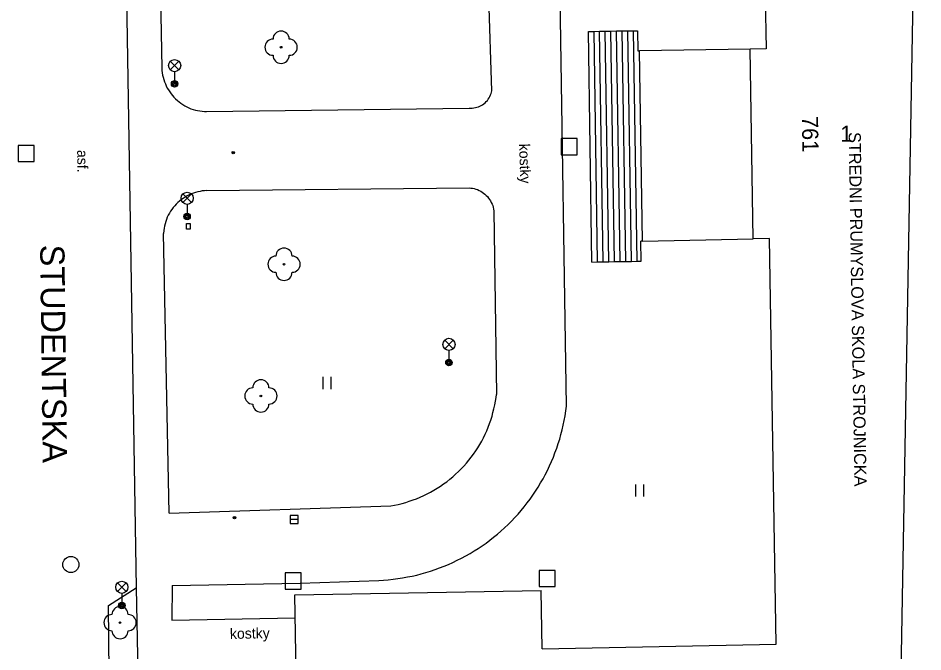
# Model space of a CAD drawing. Extents: x -641829 to -641525, y -1114855 to -1114359.
# Drawn here: x -641581.2 to -641525.3, y -1114437 to -1114397.8 of the extents above; entities that cross this region are included whole.
import ezdxf

# ---------------------------------------------------------------- set-up
doc = ezdxf.new("R2010")
doc.units = 0
for name, color, linetype in [('Vrstva 1', 7, 'Continuous'), ('Vrstva 10', 7, 'Continuous'), ('Vrstva 11', 7, 'Continuous'), ('Vrstva 20', 7, 'Continuous'), ('Vrstva 22', 7, 'Continuous'), ('Vrstva 24', 7, 'Continuous'), ('Vrstva 26', 7, 'Continuous'), ('Vrstva 27', 7, 'Continuous'), ('Vrstva 33', 7, 'Continuous'), ('Vrstva 36', 7, 'Continuous'), ('Vrstva 40', 7, 'Continuous'), ('Vrstva 41', 7, 'Continuous'), ('Vrstva 46', 7, 'Continuous'), ('Vrstva 47', 7, 'Continuous'), ('Vrstva 49', 7, 'Continuous'), ('Vrstva 5', 7, 'Continuous')]:
    doc.layers.add(name, color=color, linetype=linetype)

msp = doc.modelspace()

# ---------------------------------------------------------------- linework, layer by layer
at = {"layer": 'Vrstva 1'}
msp.add_line((-641533.66, -1114832.21), (-641525.3, -1114362.64), dxfattribs=at)
at = {"layer": 'Vrstva 10'}
for p, q in [((-641574.78, -1114379.56), (-641573.9, -1114433.06)), ((-641572.61, -1114384.05), (-641572.32, -1114400.95)), ((-641551.93, -1114402.34), (-641552.29, -1114391.15)), ((-641547.32, -1114421.83), (-641547.78, -1114391.56)), ((-641572.32, -1114400.95), (-641572.31, -1114401.09)), ((-641572.31, -1114401.09), (-641572.29, -1114401.23)), ((-641572.29, -1114401.23), (-641572.27, -1114401.37)), ((-641572.27, -1114401.37), (-641572.24, -1114401.51)), ((-641572.24, -1114401.51), (-641572.2, -1114401.64)), ((-641572.2, -1114401.64), (-641572.16, -1114401.78)), ((-641572.16, -1114401.78), (-641572.1, -1114401.91)), ((-641572.1, -1114401.91), (-641572.05, -1114402.04)), ((-641572.05, -1114402.04), (-641571.98, -1114402.17)), ((-641571.98, -1114402.17), (-641571.91, -1114402.29)), ((-641571.91, -1114402.29), (-641571.83, -1114402.41)), ((-641571.83, -1114402.41), (-641571.75, -1114402.52)), ((-641571.75, -1114402.52), (-641571.66, -1114402.64)), ((-641571.66, -1114402.64), (-641571.57, -1114402.74)), ((-641571.57, -1114402.74), (-641571.47, -1114402.84)), ((-641552.15, -1114402.86), (-641552.1, -1114402.78)), ((-641552.1, -1114402.78), (-641552.05, -1114402.69)), ((-641552.05, -1114402.69), (-641552.01, -1114402.6)), ((-641552.01, -1114402.6), (-641551.98, -1114402.51)), ((-641551.98, -1114402.51), (-641551.95, -1114402.42)), ((-641551.95, -1114402.42), (-641551.93, -1114402.34)), ((-641571.47, -1114402.84), (-641571.36, -1114402.94)), ((-641571.36, -1114402.94), (-641571.25, -1114403.03)), ((-641571.25, -1114403.03), (-641571.14, -1114403.11)), ((-641571.14, -1114403.11), (-641571.02, -1114403.19)), ((-641571.02, -1114403.19), (-641570.9, -1114403.27)), ((-641570.9, -1114403.27), (-641570.78, -1114403.33)), ((-641570.78, -1114403.33), (-641570.65, -1114403.39)), ((-641570.65, -1114403.39), (-641570.52, -1114403.45)), ((-641553.05, -1114403.4), (-641552.95, -1114403.38)), ((-641552.95, -1114403.38), (-641552.86, -1114403.36)), ((-641552.86, -1114403.36), (-641552.76, -1114403.33)), ((-641552.76, -1114403.33), (-641552.67, -1114403.29)), ((-641552.67, -1114403.29), (-641552.59, -1114403.25)), ((-641552.59, -1114403.25), (-641552.5, -1114403.2)), ((-641552.5, -1114403.2), (-641552.42, -1114403.14)), ((-641552.42, -1114403.14), (-641552.35, -1114403.08)), ((-641552.35, -1114403.08), (-641552.28, -1114403.01)), ((-641552.28, -1114403.01), (-641552.21, -1114402.94)), ((-641552.21, -1114402.94), (-641552.15, -1114402.86)), ((-641570.52, -1114403.45), (-641570.38, -1114403.49)), ((-641570.38, -1114403.49), (-641570.25, -1114403.53)), ((-641570.25, -1114403.53), (-641570.11, -1114403.57)), ((-641570.11, -1114403.57), (-641569.97, -1114403.59)), ((-641569.97, -1114403.59), (-641569.83, -1114403.61)), ((-641569.83, -1114403.61), (-641569.69, -1114403.62)), ((-641569.69, -1114403.62), (-641569.55, -1114403.63)), ((-641569.55, -1114403.63), (-641553.34, -1114403.41)), ((-641553.34, -1114403.41), (-641553.24, -1114403.41)), ((-641553.24, -1114403.41), (-641553.15, -1114403.41)), ((-641553.15, -1114403.41), (-641553.05, -1114403.4)), ((-641569.54, -1114408.51), (-641553.34, -1114408.34)), ((-641553.34, -1114408.34), (-641553.23, -1114408.35)), ((-641553.23, -1114408.35), (-641553.13, -1114408.36)), ((-641553.13, -1114408.36), (-641553.02, -1114408.39)), ((-641553.02, -1114408.39), (-641552.92, -1114408.42)), ((-641552.92, -1114408.42), (-641552.82, -1114408.45)), ((-641570.88, -1114408.91), (-641571, -1114408.99)), ((-641570.76, -1114408.84), (-641570.88, -1114408.91)), ((-641570.63, -1114408.77), (-641570.76, -1114408.84)), ((-641570.5, -1114408.72), (-641570.63, -1114408.77)), ((-641570.37, -1114408.67), (-641570.5, -1114408.72)), ((-641570.24, -1114408.62), (-641570.37, -1114408.67)), ((-641570.1, -1114408.59), (-641570.24, -1114408.62)), ((-641569.96, -1114408.56), (-641570.1, -1114408.59)), ((-641569.82, -1114408.53), (-641569.96, -1114408.56)), ((-641569.68, -1114408.52), (-641569.82, -1114408.53)), ((-641569.54, -1114408.51), (-641569.68, -1114408.52)), ((-641552.82, -1114408.45), (-641552.72, -1114408.5)), ((-641552.72, -1114408.5), (-641552.62, -1114408.55)), ((-641552.62, -1114408.55), (-641552.53, -1114408.6)), ((-641552.53, -1114408.6), (-641552.44, -1114408.66)), ((-641552.44, -1114408.66), (-641552.36, -1114408.73)), ((-641552.36, -1114408.73), (-641552.28, -1114408.81)), ((-641552.28, -1114408.81), (-641552.2, -1114408.88)), ((-641552.2, -1114408.88), (-641552.14, -1114408.97)), ((-641552.14, -1114408.97), (-641552.07, -1114409.05)), ((-641571.52, -1114409.45), (-641571.61, -1114409.56)), ((-641571.43, -1114409.35), (-641571.52, -1114409.45)), ((-641571.33, -1114409.25), (-641571.43, -1114409.35)), ((-641571.22, -1114409.16), (-641571.33, -1114409.25)), ((-641571.11, -1114409.07), (-641571.22, -1114409.16)), ((-641571, -1114408.99), (-641571.11, -1114409.07)), ((-641552.07, -1114409.05), (-641552.02, -1114409.15)), ((-641552.02, -1114409.15), (-641551.97, -1114409.24)), ((-641551.97, -1114409.24), (-641551.92, -1114409.34)), ((-641551.92, -1114409.34), (-641551.88, -1114409.44)), ((-641551.88, -1114409.44), (-641551.85, -1114409.54)), ((-641551.85, -1114409.54), (-641551.83, -1114409.65)), ((-641571.92, -1114410.03), (-641571.98, -1114410.16)), ((-641571.85, -1114409.91), (-641571.92, -1114410.03)), ((-641571.78, -1114409.79), (-641571.85, -1114409.91)), ((-641571.7, -1114409.67), (-641571.78, -1114409.79)), ((-641571.61, -1114409.56), (-641571.7, -1114409.67)), ((-641551.83, -1114409.65), (-641551.81, -1114409.77)), ((-641551.81, -1114409.77), (-641551.65, -1114421.12)), ((-641572.12, -1114410.56), (-641572.15, -1114410.7)), ((-641572.08, -1114410.43), (-641572.12, -1114410.56)), ((-641572.03, -1114410.29), (-641572.08, -1114410.43)), ((-641571.98, -1114410.16), (-641572.03, -1114410.29)), ((-641572.19, -1114410.98), (-641572.21, -1114411.16)), ((-641571.87, -1114428.45), (-641572.21, -1114411.16)), ((-641572.17, -1114410.84), (-641572.19, -1114410.98)), ((-641572.15, -1114410.7), (-641572.17, -1114410.84)), ((-641551.67, -1114421.3), (-641551.65, -1114421.12)), ((-641551.8, -1114422), (-641551.75, -1114421.76)), ((-641551.75, -1114421.76), (-641551.71, -1114421.53)), ((-641551.71, -1114421.53), (-641551.67, -1114421.3)), ((-641547.36, -1114422.13), (-641547.32, -1114421.83)), ((-641551.92, -1114422.46), (-641551.86, -1114422.23)), ((-641551.86, -1114422.23), (-641551.8, -1114422)), ((-641547.41, -1114422.43), (-641547.36, -1114422.13)), ((-641552.16, -1114423.13), (-641552.07, -1114422.91)), ((-641552.07, -1114422.91), (-641551.99, -1114422.69)), ((-641551.99, -1114422.69), (-641551.92, -1114422.46)), ((-641547.52, -1114423.01), (-641547.46, -1114422.72)), ((-641547.46, -1114422.72), (-641547.41, -1114422.43)), ((-641552.34, -1114423.57), (-641552.25, -1114423.35)), ((-641552.25, -1114423.35), (-641552.16, -1114423.13)), ((-641547.66, -1114423.58), (-641547.59, -1114423.3)), ((-641547.59, -1114423.3), (-641547.52, -1114423.01)), ((-641552.68, -1114424.2), (-641552.56, -1114423.99)), ((-641552.56, -1114423.99), (-641552.45, -1114423.78)), ((-641552.45, -1114423.78), (-641552.34, -1114423.57)), ((-641547.83, -1114424.15), (-641547.74, -1114423.87)), ((-641547.74, -1114423.87), (-641547.66, -1114423.58)), ((-641553.06, -1114424.8), (-641552.93, -1114424.6)), ((-641552.93, -1114424.6), (-641552.8, -1114424.4)), ((-641552.8, -1114424.4), (-641552.68, -1114424.2)), ((-641548.03, -1114424.71), (-641547.92, -1114424.43)), ((-641547.92, -1114424.43), (-641547.83, -1114424.15)), ((-641553.5, -1114425.36), (-641553.35, -1114425.18)), ((-641553.35, -1114425.18), (-641553.2, -1114424.99)), ((-641553.2, -1114424.99), (-641553.06, -1114424.8)), ((-641548.25, -1114425.26), (-641548.13, -1114424.99)), ((-641548.13, -1114424.99), (-641548.03, -1114424.71)), ((-641553.99, -1114425.88), (-641553.82, -1114425.71)), ((-641553.82, -1114425.71), (-641553.66, -1114425.54)), ((-641553.66, -1114425.54), (-641553.5, -1114425.36)), ((-641548.5, -1114425.8), (-641548.37, -1114425.53)), ((-641548.37, -1114425.53), (-641548.25, -1114425.26)), ((-641554.53, -1114426.35), (-641554.35, -1114426.2)), ((-641554.35, -1114426.2), (-641554.17, -1114426.04)), ((-641554.17, -1114426.04), (-641553.99, -1114425.88)), ((-641548.77, -1114426.33), (-641548.63, -1114426.07)), ((-641548.63, -1114426.07), (-641548.5, -1114425.8)), ((-641555.3, -1114426.91), (-641555.1, -1114426.78)), ((-641555.1, -1114426.78), (-641554.91, -1114426.64)), ((-641554.91, -1114426.64), (-641554.72, -1114426.5)), ((-641554.72, -1114426.5), (-641554.53, -1114426.35)), ((-641549.24, -1114427.09), (-641549.07, -1114426.84)), ((-641549.07, -1114426.84), (-641548.92, -1114426.58)), ((-641548.92, -1114426.58), (-641548.77, -1114426.33)), ((-641556.36, -1114427.46), (-641556.14, -1114427.36)), ((-641556.14, -1114427.36), (-641555.93, -1114427.25)), ((-641555.93, -1114427.25), (-641555.72, -1114427.14)), ((-641555.72, -1114427.14), (-641555.51, -1114427.03)), ((-641555.51, -1114427.03), (-641555.3, -1114426.91)), ((-641549.57, -1114427.58), (-641549.4, -1114427.33)), ((-641549.4, -1114427.33), (-641549.24, -1114427.09)), ((-641571.87, -1114428.45), (-641558.18, -1114427.99)), ((-641558.18, -1114427.99), (-641557.95, -1114427.95)), ((-641557.95, -1114427.95), (-641557.71, -1114427.9)), ((-641557.71, -1114427.9), (-641557.48, -1114427.84)), ((-641557.48, -1114427.84), (-641557.25, -1114427.78)), ((-641557.25, -1114427.78), (-641557.03, -1114427.71)), ((-641557.03, -1114427.71), (-641556.8, -1114427.63)), ((-641556.8, -1114427.63), (-641556.58, -1114427.55)), ((-641556.58, -1114427.55), (-641556.36, -1114427.46)), ((-641549.93, -1114428.05), (-641549.75, -1114427.81)), ((-641549.75, -1114427.81), (-641549.57, -1114427.58)), ((-641550.52, -1114428.72), (-641550.31, -1114428.5)), ((-641550.31, -1114428.5), (-641550.12, -1114428.28)), ((-641550.12, -1114428.28), (-641549.93, -1114428.05)), ((-641550.93, -1114429.14), (-641550.72, -1114428.94)), ((-641550.72, -1114428.94), (-641550.52, -1114428.72)), ((-641551.59, -1114429.74), (-641551.37, -1114429.55)), ((-641551.37, -1114429.55), (-641551.15, -1114429.35)), ((-641551.15, -1114429.35), (-641550.93, -1114429.14)), ((-641552.29, -1114430.29), (-641552.05, -1114430.11)), ((-641552.05, -1114430.11), (-641551.82, -1114429.93)), ((-641551.82, -1114429.93), (-641551.59, -1114429.74)), ((-641553.28, -1114430.94), (-641553.03, -1114430.78)), ((-641553.03, -1114430.78), (-641552.78, -1114430.63)), ((-641552.78, -1114430.63), (-641552.53, -1114430.46)), ((-641552.53, -1114430.46), (-641552.29, -1114430.29)), ((-641554.07, -1114431.36), (-641553.8, -1114431.23)), ((-641553.8, -1114431.23), (-641553.54, -1114431.08)), ((-641553.54, -1114431.08), (-641553.28, -1114430.94)), ((-641555.44, -1114431.93), (-641555.16, -1114431.83)), ((-641555.16, -1114431.83), (-641554.88, -1114431.72)), ((-641554.88, -1114431.72), (-641554.61, -1114431.61)), ((-641554.61, -1114431.61), (-641554.34, -1114431.49)), ((-641554.34, -1114431.49), (-641554.07, -1114431.36)), ((-641557.74, -1114432.49), (-641557.45, -1114432.45)), ((-641557.45, -1114432.45), (-641557.15, -1114432.39)), ((-641557.15, -1114432.39), (-641556.86, -1114432.33)), ((-641556.86, -1114432.33), (-641556.57, -1114432.27)), ((-641556.57, -1114432.27), (-641556.29, -1114432.19)), ((-641556.29, -1114432.19), (-641556, -1114432.11)), ((-641556, -1114432.11), (-641555.72, -1114432.02)), ((-641555.72, -1114432.02), (-641555.44, -1114431.93)), ((-641571.69, -1114432.92), (-641563.77, -1114432.77)), ((-641563.77, -1114432.77), (-641558.92, -1114432.6)), ((-641558.92, -1114432.6), (-641558.62, -1114432.58)), ((-641558.62, -1114432.58), (-641558.33, -1114432.56)), ((-641558.33, -1114432.56), (-641558.03, -1114432.53)), ((-641558.03, -1114432.53), (-641557.74, -1114432.49)), ((-641575.62, -1114434.15), (-641573.9, -1114433.06)), ((-641575.3, -1114465.98), (-641575.62, -1114434.15))]:
    msp.add_line(p, q, dxfattribs=at)
at = {"layer": 'Vrstva 11'}
for p, q in [((-641545.76, -1114412.93), (-641545.97, -1114398.67)), ((-641545.97, -1114398.67), (-641545.62, -1114398.67)), ((-641545.62, -1114398.67), (-641545.27, -1114398.66)), ((-641545.41, -1114412.92), (-641545.62, -1114398.67)), ((-641545.06, -1114412.92), (-641545.27, -1114398.66)), ((-641545.27, -1114398.66), (-641544.92, -1114398.66)), ((-641544.92, -1114398.66), (-641544.57, -1114398.65)), ((-641544.7, -1114412.91), (-641544.92, -1114398.66)), ((-641544.57, -1114398.65), (-641544.22, -1114398.64)), ((-641544.36, -1114412.9), (-641544.57, -1114398.65)), ((-641544.01, -1114412.9), (-641544.22, -1114398.64)), ((-641544.22, -1114398.64), (-641543.87, -1114398.64)), ((-641543.87, -1114398.64), (-641543.52, -1114398.63)), ((-641543.66, -1114412.89), (-641543.87, -1114398.64)), ((-641543.31, -1114412.89), (-641543.52, -1114398.63)), ((-641543.52, -1114398.63), (-641543.17, -1114398.63)), ((-641542.95, -1114412.88), (-641543.17, -1114398.63)), ((-641543.17, -1114398.63), (-641542.94, -1114398.63)), ((-641542.94, -1114398.63), (-641542.92, -1114399.88)), ((-641542.92, -1114399.88), (-641542.8, -1114399.87)), ((-641535.98, -1114399.76), (-641542.8, -1114399.87)), ((-641542.62, -1114411.63), (-641542.8, -1114399.87)), ((-641542.7, -1114412.88), (-641542.72, -1114411.63)), ((-641542.62, -1114411.63), (-641542.72, -1114411.63)), ((-641542.62, -1114411.63), (-641535.78, -1114411.5)), ((-641544.01, -1114412.9), (-641543.66, -1114412.89)), ((-641543.66, -1114412.89), (-641543.31, -1114412.89)), ((-641543.31, -1114412.89), (-641542.95, -1114412.88)), ((-641542.95, -1114412.88), (-641542.7, -1114412.88)), ((-641545.76, -1114412.93), (-641545.41, -1114412.92)), ((-641545.41, -1114412.92), (-641545.06, -1114412.92)), ((-641545.06, -1114412.92), (-641544.7, -1114412.91)), ((-641544.7, -1114412.91), (-641544.36, -1114412.9)), ((-641544.36, -1114412.9), (-641544.01, -1114412.9)), ((-641571.69, -1114432.92), (-641571.7, -1114435.05)), ((-641573.9, -1114433.06), (-641573.34, -1114460.63)), ((-641571.7, -1114435.05), (-641564.09, -1114434.91))]:
    msp.add_line(p, q, dxfattribs=at)
at = {"layer": 'Vrstva 20'}
for centre, radius in [((-641567.91, -1114406.17), 0.075), ((-641567.91, -1114406.17), 0.0204), ((-641567.83, -1114428.73), 0.075), ((-641567.83, -1114428.73), 0.0204)]:
    msp.add_circle(centre, radius, dxfattribs=at)
at = {"layer": 'Vrstva 22'}
for centre in [(-641564.95, -1114399.65), (-641564.77, -1114413.06), (-641566.2, -1114421.2), (-641574.9, -1114435.21)]:
    msp.add_circle(centre, 0.05, dxfattribs=at)
for centre, start, end in [((-641564.95, -1114399.15), 0, 180), ((-641565.45, -1114399.65), 90, 270), ((-641564.45, -1114399.65), 270, 90), ((-641564.95, -1114400.15), 180, 0), ((-641564.77, -1114412.56), 0, 180), ((-641565.27, -1114413.06), 90, 270), ((-641564.27, -1114413.06), 270, 90), ((-641564.77, -1114413.56), 180, 0), ((-641566.7, -1114421.2), 90, 270), ((-641566.2, -1114420.7), 0, 180), ((-641565.7, -1114421.2), 270, 90), ((-641566.2, -1114421.7), 180, 0), ((-641574.9, -1114434.71), 0, 180), ((-641575.4, -1114435.21), 90, 270), ((-641574.4, -1114435.21), 270, 90), ((-641574.9, -1114435.71), 180, 0)]:
    msp.add_arc(centre, 0.5, start, end, dxfattribs=at)
at = {"layer": 'Vrstva 24'}
msp.add_lwpolyline([(-641570.8, -1114410.89), (-641570.8, -1114410.54), (-641570.56, -1114410.54), (-641570.56, -1114410.89), (-641570.8, -1114410.89)], dxfattribs=at)
at = {"layer": 'Vrstva 26'}
for points in [[(-641546.65, -1114405.29), (-641547.65, -1114405.29), (-641547.65, -1114406.29), (-641546.65, -1114406.29)], [(-641580.2, -1114405.72), (-641581.2, -1114405.72), (-641581.2, -1114406.72), (-641580.2, -1114406.72)], [(-641563.71, -1114432.14), (-641564.71, -1114432.14), (-641564.71, -1114433.14), (-641563.71, -1114433.14)], [(-641548.01, -1114431.98), (-641549.01, -1114431.98), (-641549.01, -1114432.98), (-641548.01, -1114432.98)]]:
    msp.add_lwpolyline(points, close=True, dxfattribs=at)
at = {"layer": 'Vrstva 27'}
msp.add_line((-641563.89, -1114428.84), (-641564.39, -1114428.84), dxfattribs=at)
msp.add_lwpolyline([(-641563.89, -1114428.59), (-641564.39, -1114428.59), (-641564.39, -1114429.09), (-641563.89, -1114429.09)], close=True, dxfattribs=at)
msp.add_circle((-641577.94, -1114431.62), 0.5, dxfattribs=at)
at = {"layer": 'Vrstva 33'}
for p, q in [((-641571.795, -1114401.05), (-641571.265, -1114400.52)), ((-641571.795, -1114400.52), (-641571.265, -1114401.05)), ((-641571.53, -1114401.16), (-641571.53, -1114401.91)), ((-641571.025, -1114409.25), (-641570.495, -1114408.72)), ((-641571.025, -1114408.72), (-641570.495, -1114409.25)), ((-641570.76, -1114409.36), (-641570.76, -1114410.11)), ((-641554.844, -1114418.28), (-641554.316, -1114417.75)), ((-641554.844, -1114417.75), (-641554.316, -1114418.28)), ((-641554.58, -1114418.39), (-641554.58, -1114419.14)), ((-641575.055, -1114433.29), (-641574.525, -1114432.76)), ((-641575.055, -1114432.76), (-641574.525, -1114433.29)), ((-641574.79, -1114433.4), (-641574.79, -1114434.15))]:
    msp.add_line(p, q, dxfattribs=at)
for centre, radius in [((-641571.53, -1114400.785), 0.375), ((-641571.53, -1114401.91), 0.2), ((-641571.53, -1114401.91), 0.145), ((-641571.53, -1114401.91), 0.0876), ((-641570.76, -1114408.985), 0.375), ((-641570.76, -1114410.11), 0.2), ((-641570.76, -1114410.11), 0.145), ((-641570.76, -1114410.11), 0.0876), ((-641554.58, -1114418.015), 0.375), ((-641554.58, -1114419.14), 0.2), ((-641554.58, -1114419.14), 0.145), ((-641554.58, -1114419.14), 0.0876), ((-641574.79, -1114433.025), 0.375), ((-641574.79, -1114434.15), 0.2), ((-641574.79, -1114434.15), 0.145), ((-641574.79, -1114434.15), 0.0876)]:
    msp.add_circle(centre, radius, dxfattribs=at)
at = {"layer": 'Vrstva 36'}
for p, q in [((-641562.354, -1114420.774), (-641562.354, -1114420.022)), ((-641561.854, -1114420.774), (-641561.854, -1114420.022)), ((-641543.044, -1114427.422), (-641543.044, -1114426.674)), ((-641542.544, -1114427.422), (-641542.544, -1114426.674))]:
    msp.add_line(p, q, dxfattribs=at)
at = {"layer": 'Vrstva 5'}
for p, q in [((-641535.44, -1114374.64), (-641534.98, -1114399.74)), ((-641534.98, -1114399.74), (-641535.98, -1114399.76)), ((-641535.78, -1114411.5), (-641535.98, -1114399.76)), ((-641534.78, -1114411.48), (-641535.78, -1114411.5)), ((-641534.36, -1114436.54), (-641534.78, -1114411.48)), ((-641564.11, -1114433.5), (-641548.88, -1114433.23)), ((-641563.03, -1114493.34), (-641564.11, -1114433.5)), ((-641548.82, -1114436.83), (-641548.88, -1114433.23)), ((-641548.82, -1114436.83), (-641534.36, -1114436.54))]:
    msp.add_line(p, q, dxfattribs=at)

# ---------------------------------------------------------------- texts
at = {"layer": 'Vrstva 40'}
for s, height, rotation, p in [('asf.', 0.65, 270.7007, (-641577.55, -1114406)), ('kostky', 0.6499, 271.8427, (-641550.25, -1114405.62)), ('kostky', 0.65, 1.0338, (-641568.11, -1114436.22))]:
    msp.add_text(s, height=height, rotation=rotation, dxfattribs=at).set_placement(p)
at = {"layer": 'Vrstva 41'}
msp.add_text('STREDNI PRUMYSLOVA SKOLA STROJNICKA', height=0.7499, rotation=270.9516, dxfattribs=at).set_placement((-641529.89, -1114404.9))
at = {"layer": 'Vrstva 46'}
msp.add_text('1', height=1, dxfattribs=at).set_placement((-641530.4, -1114405.49))
at = {"layer": 'Vrstva 47'}
msp.add_text('761', height=0.9999, rotation=270.9516, dxfattribs=at).set_placement((-641532.78, -1114403.91))
at = {"layer": 'Vrstva 49'}
msp.add_text('STUDENTSKA', height=1.5, rotation=270.7007, dxfattribs=at).set_placement((-641579.84, -1114411.86))

doc.saveas('drawing.dxf')
